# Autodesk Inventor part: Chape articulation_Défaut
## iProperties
Shininess: 64.0
Length Units: 11269
Angle Units: 11279
Time Units: 11290
Mass Units: 11283
Length Display Precision: 3
Angle Display Precision: 2
Compacted: True
Part Number: Chape articulation_Défaut
Document SubType Name: Modeling
Created: 2006-01
Material: Par défaut
Designer: Fricot
Density: 0.0
Volumn: 0.0
Area: 0.0
PropertySet Name: Model Information
Control State: 0
Master: False
Checked Out: False
Author: Fricot
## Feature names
1. Base1
